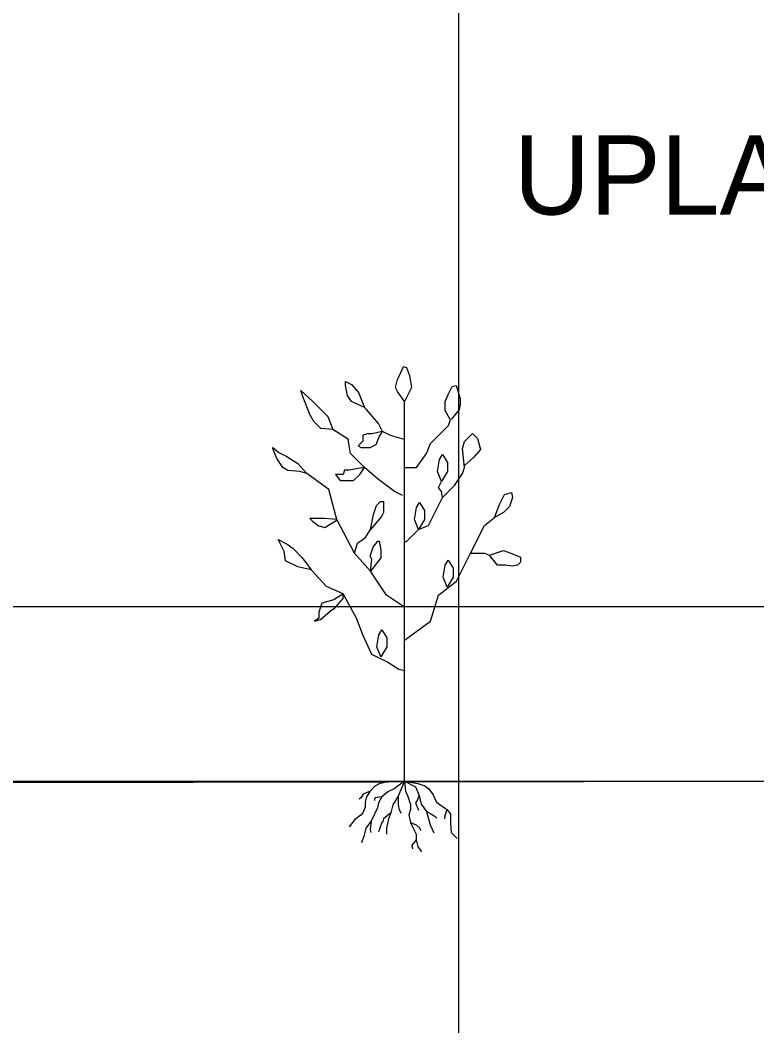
# Model space of a CAD drawing. Extents: x 1578769 to 1579225, y 724002 to 724828.
# Drawn here: x 1578841.42 to 1578846.08, y 724320.5 to 724326.86 of the extents above; entities that cross this region are included whole.
import ezdxf

# ---------------------------------------------------------------- set-up
doc = ezdxf.new("R2010")
doc.units = 0
for name, color, linetype in [('1', 7, 'Continuous'), ('Default', 7, 'Continuous'), ('Old_Level_41', 7, 'Continuous'), ('R_Exist Surface', 7, 'Continuous')]:
    doc.layers.add(name, color=color, linetype=linetype)

msp = doc.modelspace()

# ---------------------------------------------------------------- linework, layer by layer
at = {"layer": '1'}
for p, q in [((1578843.8529, 724322.0487), (1578843.8529, 724324.4487)), ((1578843.8576, 724322.0437), (1578843.8594, 724322.0477))]:
    msp.add_line(p, q, dxfattribs=at)
for points in [[(1578843.8529, 724324.4487), (1578843.8088, 724324.5118), (1578843.7962, 724324.5371), (1578843.8088, 724324.5876), (1578843.8214, 724324.6129), (1578843.8467, 724324.6697), (1578843.8656, 724324.6634), (1578843.8845, 724324.6129), (1578843.8908, 724324.575), (1578843.8971, 724324.5371)], [(1578843.6005, 724324.4108), (1578843.5185, 724324.4487), (1578843.4932, 724324.4866), (1578843.4806, 724324.5497), (1578843.4806, 724324.575), (1578843.5185, 724324.5561), (1578843.5626, 724324.5055)], [(1578843.3985, 724324.2718), (1578843.3228, 724324.2782), (1578843.2787, 724324.3224), (1578843.2534, 724324.3666), (1578843.2092, 724324.4803), (1578843.1966, 724324.5182), (1578843.2723, 724324.4487), (1578843.3165, 724324.4045), (1578843.367, 724324.354)], [(1578843.7141, 724324.2592), (1578843.6455, 724324.2446), (1578843.6169, 724324.2446), (1578843.5882, 724324.235), (1578843.5882, 724324.1968), (1578843.5596, 724324.1681), (1578843.5787, 724324.1586), (1578843.636, 724324.1586), (1578843.6741, 724324.1777), (1578843.6932, 724324.2255)], [(1578843.6005, 724324.0318), (1578843.5596, 724324.0248), (1578843.5023, 724324.0153), (1578843.4737, 724324.0153), (1578843.4641, 724323.9866), (1578843.4164, 724323.9866), (1578843.445, 724323.9484), (1578843.4832, 724323.9484), (1578843.5309, 724323.9484), (1578843.5691, 724323.9866)], [(1578843.6384, 724323.6403), (1578843.6573, 724323.735), (1578843.6699, 724323.7729), (1578843.6762, 724323.7919), (1578843.7015, 724323.8171), (1578843.7204, 724323.8171), (1578843.7204, 724323.7476), (1578843.7078, 724323.7224)], [(1578843.2636, 724323.3848), (1578843.1777, 724323.4039), (1578843.1014, 724323.4421), (1578843.0918, 724323.4994), (1578843.0536, 724323.5758), (1578843.1109, 724323.5472), (1578843.1491, 724323.5185), (1578843.2064, 724323.4612), (1578843.235, 724323.423)], [(1578843.6383, 724323.375), (1578843.6455, 724323.4516), (1578843.636, 724323.4707), (1578843.6551, 724323.5281), (1578843.6837, 724323.5663), (1578843.6932, 724323.5663), (1578843.7028, 724323.5089), (1578843.7028, 724323.4612)], [(1578843.4641, 724323.2319), (1578843.4068, 724323.1937), (1578843.3305, 724323.1746), (1578843.3114, 724323.1173), (1578843.3114, 724323.079), (1578843.2827, 724323.0599), (1578843.3209, 724323.0695), (1578843.3973, 724323.1364), (1578843.4068, 724323.1364), (1578843.4641, 724323.2032)]]:
    msp.add_lwpolyline(points, close=True, dxfattribs=at)
for points in [[(1578844.1401, 724324.335), (1578844.1085, 724324.3918), (1578844.1085, 724324.4487), (1578844.1275, 724324.4929), (1578844.1527, 724324.5434), (1578844.178, 724324.5497), (1578844.2032, 724324.4676), (1578844.2032, 724324.4297), (1578844.1969, 724324.3982), (1578844.1464, 724324.335)], [(1578843.8529, 724324.2087), (1578843.7646, 724324.2339), (1578843.7141, 724324.2592), (1578843.6888, 724324.3097), (1578843.6131, 724324.3981), (1578843.6005, 724324.4108)], [(1578843.8529, 724324.0318), (1578843.9286, 724324.0318), (1578843.9918, 724324.1203), (1578844.017, 724324.1834), (1578844.1306, 724324.2971), (1578844.1432, 724324.335)], [(1578843.8403, 724323.855), (1578843.7898, 724323.8803), (1578843.6888, 724323.9561), (1578843.6005, 724324.0318), (1578843.5121, 724324.1203), (1578843.4995, 724324.196), (1578843.4995, 724324.2087), (1578843.3985, 724324.2718)], [(1578844.2316, 724324.0318), (1578844.219, 724324.1518), (1578844.2316, 724324.1961), (1578844.2821, 724324.2466), (1578844.3137, 724324.215), (1578844.3326, 724324.1455), (1578844.2884, 724324.095), (1578844.2316, 724324.0445)], [(1578843.2344, 724323.9939), (1578843.1903, 724324.0066), (1578843.1146, 724324.0129), (1578843.083, 724324.0319), (1578843.0451, 724324.0887), (1578843.0199, 724324.1518), (1578843.0199, 724324.1582), (1578843.0578, 724324.1266), (1578843.1082, 724324.1013), (1578843.1777, 724324.0571), (1578843.2344, 724323.9939)], [(1578844.0864, 724323.9434), (1578844.0612, 724324.0066), (1578844.0738, 724324.0824), (1578844.0927, 724324.114), (1578844.1243, 724324.0634), (1578844.1243, 724324.0066), (1578844.0864, 724323.9434)], [(1578843.8529, 724323.1477), (1578843.7393, 724323.2234), (1578843.6383, 724323.375), (1578843.5374, 724323.4887), (1578843.4238, 724323.7034), (1578843.3733, 724323.8929), (1578843.2344, 724323.9939)], [(1578843.8529, 724323.5645), (1578843.8655, 724323.5645), (1578843.9413, 724323.6403), (1578844.0044, 724323.6655), (1578844.0927, 724323.8424), (1578844.1685, 724323.9182), (1578844.219, 724323.9939), (1578844.2316, 724324.0318)], [(1578844.0927, 724323.8424), (1578844.0864, 724323.8803), (1578844.0675, 724323.9055), (1578844.0864, 724323.9434)], [(1578844.4209, 724323.7161), (1578844.4525, 724323.7982), (1578844.4841, 724323.8613), (1578844.5282, 724323.874), (1578844.5346, 724323.8424), (1578844.5156, 724323.7856), (1578844.4778, 724323.7477), (1578844.4209, 724323.7161)], [(1578843.9413, 724323.6403), (1578843.916, 724323.7034), (1578843.9286, 724323.7792), (1578843.9476, 724323.8108), (1578843.9791, 724323.7603), (1578843.9791, 724323.7034), (1578843.9413, 724323.6403)], [(1578843.4238, 724323.7034), (1578843.3496, 724323.7096), (1578843.2923, 724323.7096), (1578843.2541, 724323.7096), (1578843.2732, 724323.6905), (1578843.3114, 724323.6618), (1578843.3496, 724323.6522), (1578843.4259, 724323.7)], [(1578843.8529, 724322.9398), (1578844.017, 724323.0592), (1578844.0675, 724323.2234), (1578844.1811, 724323.3119), (1578844.2694, 724323.4887), (1578844.3578, 724323.6655), (1578844.4209, 724323.7161)], [(1578843.5374, 724323.4887), (1578843.5563, 724323.5519), (1578843.6068, 724323.5898), (1578843.6384, 724323.6403)], [(1578844.2694, 724323.4887), (1578844.3326, 724323.4887), (1578844.3578, 724323.4887), (1578844.3894, 724323.4761)], [(1578844.3894, 724323.4761), (1578844.4777, 724323.5076), (1578844.5409, 724323.4824), (1578844.585, 724323.4634), (1578844.585, 724323.4319), (1578844.5661, 724323.4129), (1578844.5345, 724323.4066), (1578844.4904, 724323.4129), (1578844.4399, 724323.4129), (1578844.3894, 724323.4761)], [(1578844.1223, 724323.2747), (1578844.097, 724323.3378), (1578844.1096, 724323.4136), (1578844.1286, 724323.4452), (1578844.1601, 724323.3947), (1578844.1601, 724323.3378), (1578844.1223, 724323.2747)], [(1578843.8555, 724322.7447), (1578843.8174, 724322.7542), (1578843.741, 724322.802), (1578843.6455, 724322.8498), (1578843.5882, 724322.974), (1578843.55, 724323.079), (1578843.4641, 724323.2319), (1578843.3591, 724323.2797), (1578843.2636, 724323.3848), (1578843.2636, 724323.3848)], [(1578843.7022, 724322.8352), (1578843.677, 724322.8984), (1578843.6896, 724322.9742), (1578843.7085, 724323.0058), (1578843.7401, 724322.9552), (1578843.7401, 724322.8984), (1578843.7022, 724322.8352)], [(1578843.8529, 724322.0487), (1578843.8015, 724322.0429), (1578843.786, 724322.0468), (1578843.7278, 724322.039), (1578843.6929, 724322.0313), (1578843.6657, 724322.0157), (1578843.6347, 724321.9847), (1578843.6114, 724321.9497), (1578843.6036, 724321.9148), (1578843.6036, 724321.8837), (1578843.5881, 724321.8488), (1578843.5765, 724321.8333), (1578843.5377, 724321.8061), (1578843.5028, 724321.7595)], [(1578843.8529, 724322.0487), (1578843.786, 724322.0002), (1578843.7472, 724321.9808), (1578843.7084, 724321.9497), (1578843.689, 724321.9109), (1578843.6812, 724321.8798), (1578843.6424, 724321.7945), (1578843.6075, 724321.7517), (1578843.5959, 724321.7013), (1578843.5804, 724321.6585)], [(1578843.8529, 724322.0487), (1578843.8131, 724321.9536), (1578843.7782, 724321.8993), (1578843.7666, 724321.8488), (1578843.7511, 724321.81), (1578843.7395, 724321.7517), (1578843.7395, 724321.7129)], [(1578843.8529, 724322.0487), (1578843.9369, 724322.0326), (1578843.98, 724322.0196), (1578844.0071, 724322.0002), (1578844.0343, 724321.9614), (1578844.0537, 724321.9148), (1578844.1196, 724321.8682), (1578844.1429, 724321.841), (1578844.1429, 724321.7828), (1578844.1468, 724321.7246), (1578844.1856, 724321.6857)], [(1578843.8529, 724322.0487), (1578843.9218, 724322.0118), (1578843.9451, 724321.9575), (1578843.9567, 724321.9031), (1578843.9916, 724321.8566), (1578844.0149, 724321.7711), (1578844.0382, 724321.7207)], [(1578843.8529, 724322.0487), (1578843.8597, 724321.9847), (1578843.8713, 724321.9575), (1578843.883, 724321.9187), (1578843.8907, 724321.9031), (1578843.8907, 724321.8721), (1578843.8791, 724321.8333), (1578843.8907, 724321.7867), (1578843.9063, 724321.7517), (1578843.9256, 724321.7129), (1578843.9256, 724321.678), (1578843.9373, 724321.6353), (1578843.9606, 724321.6003)], [(1578843.6347, 724321.9847), (1578843.592, 724321.9653), (1578843.5765, 724321.942), (1578843.5649, 724321.9342)], [(1578843.9451, 724321.9575), (1578843.9334, 724321.9264), (1578843.9218, 724321.9109), (1578843.9412, 724321.8643)], [(1578843.7084, 724321.9497), (1578843.6657, 724321.942), (1578843.6618, 724321.9264)], [(1578843.8131, 724321.9536), (1578843.8131, 724321.8993), (1578843.817, 724321.876), (1578843.8287, 724321.8449)], [(1578843.7666, 724321.8488), (1578843.72, 724321.81), (1578843.7162, 724321.7906), (1578843.7084, 724321.7867), (1578843.689, 724321.7284)], [(1578843.9916, 724321.8566), (1578844.0265, 724321.8371), (1578844.0459, 724321.8255), (1578844.0576, 724321.8139)], [(1578844.1196, 724321.8682), (1578844.108, 724321.8294), (1578844.1041, 724321.81)], [(1578843.6424, 724321.7945), (1578843.6347, 724321.7401), (1578843.6386, 724321.7246)], [(1578843.8907, 724321.7867), (1578843.9256, 724321.7711), (1578843.9489, 724321.7517), (1578843.9528, 724321.7362)], [(1578843.9256, 724321.678), (1578843.8985, 724321.643), (1578843.9024, 724321.6197)]]:
    msp.add_lwpolyline(points, dxfattribs=at)
at = {"layer": 'Default'}
msp.add_lwpolyline([(1578822.9439, 724322.1501), (1578824.3539, 724322.1046), (1578827.2539, 724322.0875), (1578831.4239, 724322.0631), (1578836.8239, 724322.0314), (1578858.5939, 724322.0681), (1578861.1339, 724322.0669), (1578862.9439, 724322.0712), (1578882.4539, 724322.0121), (1578884.5239, 724320.4129), (1578890.3939, 724312.7963), (1578905.4439, 724309.3885), (1578918.1239, 724306.8519), (1578923.7639, 724306.9982), (1578939.0039, 724307.3934), (1578947.2439, 724307.6071), (1578961.8739, 724307.8524), (1578966.5939, 724307.868), (1579023.7239, 724312.4122), (1579059.0839, 724315.3747), (1579126.2439, 724320.0384), (1579145.7939, 724321.276)], dxfattribs=at)
at = {"layer": 'Old_Level_41'}
msp.add_line((1578844.1939, 724333.1501), (1578844.1939, 724303.1501), dxfattribs=at)
msp.add_lwpolyline([(1578924.1939, 724323.1501), (1578824.1939, 724323.1501)], dxfattribs=at)
at = {"layer": 'R_Exist Surface'}
msp.add_lwpolyline([(1578824.1939, 724322.1622), (1578829.284, 724322.0912), (1578836.2755, 724322.0556), (1578841.2426, 724322.0491), (1578852.2427, 724322.0476), (1578866.2522, 724322.0925), (1578877.2091, 724322.0144), (1578882.2159, 724322.036), (1578883.2289, 724321.4278), (1578884.2158, 724320.6364), (1578885.2591, 724319.5036), (1578887.3767, 724316.6913), (1578890.5015, 724312.7881), (1578895.2522, 724311.6936), (1578904.139, 724309.6792), (1578908.2007, 724308.813), (1578914.4913, 724307.5769), (1578918.1855, 724306.8444), (1578924.1939, 724307.0119)], dxfattribs=at)

# ---------------------------------------------------------------- texts
at = {"layer": '1'}
msp.add_text('UPLAND', height=0.5, dxfattribs=at).set_placement((1578844.5425, 724325.6308))

doc.saveas('drawing.dxf')
